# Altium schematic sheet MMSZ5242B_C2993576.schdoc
size 127 x 101 mm
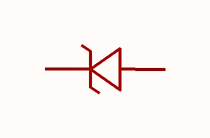
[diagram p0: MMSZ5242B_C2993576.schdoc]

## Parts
D?  mmsz5242b_c2993576  [SOD-123_L2.7-W1.6-LS3.7-RD]  (value not drawn)

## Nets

Not connected (* = marked no-connect by the designer): D? 1(C) 2(A)

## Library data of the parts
D? = mmsz5242b_c2993576: 二极管配置:1个独立式;稳压值(标称值):12V;稳压值(范围):11.4V~12.6V;耗散功率(Pd):500mW;; Manufacturer: MDD(辰达半导体); AddInBom: yes; ModelId: ad7e39f9e5534b3c96ffdc5532ebb493; ModelName: SOD-123_L2.7-W1.6-H1.4-LS3.7; ModelTransform: 146.026,62.992,0,180,0,0,0.0005,0,0; Diode Configuration: 1个独立式; Zener Voltage(Nom): 12V; Reverse Leakage Current (Ir): 1uA@9.1V; Pd - Power Dissipation: 500mW; Impedance(Zzt): 30Ω; Impedance(Zzk): 600Ω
